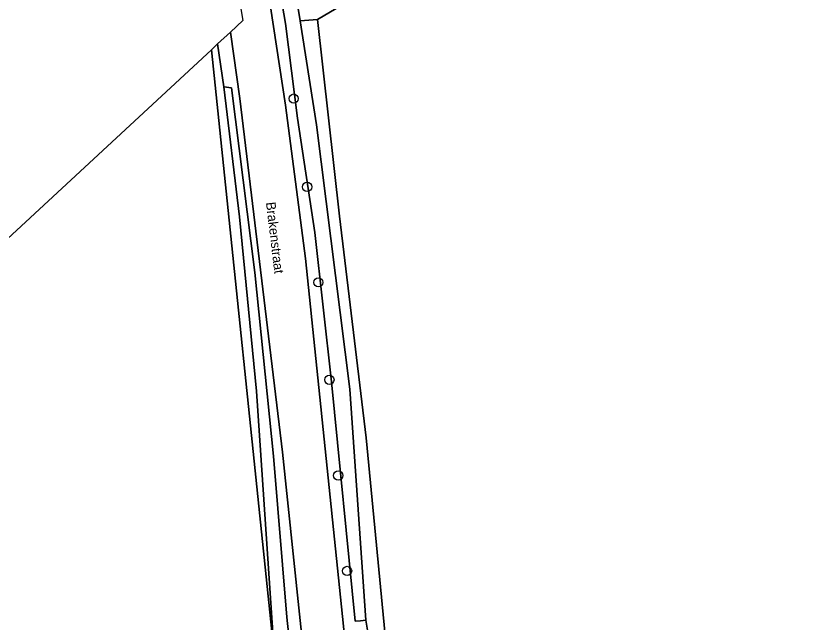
# Model space of a CAD drawing. Extents: x 163859 to 164644, y 379566 to 382155.
# Drawn here: x 164337.9 to 164422.2, y 382026.8 to 382090.8 of the extents above; entities that cross this region are included whole.
import ezdxf

# ---------------------------------------------------------------- set-up
doc = ezdxf.new("R2010")
doc.units = 0
for name, color, linetype in [('IMGEO_Boom', 7, 'Continuous'), ('IMGEO_Erf', 7, 'Continuous'), ('IMGEO_Grasland_agrarisch', 7, 'Continuous'), ('IMGEO_Grasland_overig', 7, 'Continuous'), ('IMGEO_Groenvoorziening', 7, 'Continuous'), ('IMGEO_Hek', 7, 'Continuous'), ('IMGEO_Loofbos', 7, 'Continuous'), ('IMGEO_Openbare_ruimte_label', 7, 'Continuous'), ('IMGEO_Rijbaan_lokaal_halfverhard', 7, 'Continuous'), ('IMGEO_Waterloop', 7, 'Continuous')]:
    doc.layers.add(name, color=color, linetype=linetype)

msp = doc.modelspace()

# ---------------------------------------------------------------- linework, layer by layer
at = {"layer": 'IMGEO_Boom'}
for centre in [(164367.083, 382082.063), (164368.496, 382072.769), (164369.681, 382062.713), (164370.841, 382052.454), (164371.772, 382042.372), (164372.703, 382032.316)]:
    msp.add_circle(centre, 0.489, dxfattribs=at)
at = {"layer": 'IMGEO_Erf'}
msp.add_lwpolyline([(164367.356, 382092.892), (164367.768, 382090.275), (164369.59, 382090.415), (164373.957, 382092.98)], dxfattribs=at)
msp.add_lwpolyline([(164358.416, 382087.209), (164254.852, 381991.262), (164247.66, 381997.032), (164147.193, 381903.339), (164170.551, 381887.103), (164176.8, 381882.795), (164180.902, 381879.968), (164183.031, 381877.576), (164194.945, 381868.909), (164195.394, 381868.583), (164197.248, 381870.262), (164204.736, 381876.958), (164229.912, 381895.792), (164270.687, 381927.48), (164301.861, 381952.134), (164302.429, 381952.58), (164302.08, 381953.025), (164345.159, 381986.829), (164370.617, 381969.688), (164370.447, 381973.615), (164369.98, 381979.405), (164367.666, 382000), (164365.056, 382023.236)], close=True, dxfattribs=at)
at = {"layer": 'IMGEO_Grasland_agrarisch'}
msp.add_lwpolyline([(164435.91, 382115.587), (164393.78, 382126.007), (164393.977, 382126.658), (164393.22, 382126.843), (164389.6, 382112.906), (164387.831, 382106.038), (164385.986, 382095.611), (164373.957, 382092.98), (164369.59, 382090.415), (164371.919, 382069.694), (164374.733, 382046.331), (164377.32, 382019.353)], dxfattribs=at)
at = {"layer": 'IMGEO_Grasland_overig'}
msp.add_lwpolyline([(164380.198, 381977.725), (164381.786, 381978.083), (164380.199, 381990.41), (164377.32, 382019.353), (164374.733, 382046.331), (164371.919, 382069.694), (164369.59, 382090.415), (164367.768, 382090.275), (164368.053, 382088.47), (164369.499, 382079.302), (164372.988, 382051.449), (164374.694, 382027.134), (164374.98, 382025.233), (164375.002, 382024.987), (164377.319, 381999.913), (164378.624, 381987.802), (164379.45, 381980.132), (164379.718, 381978.949), (164379.996, 381979.003)], close=True, dxfattribs=at)
at = {"layer": 'IMGEO_Groenvoorziening'}
for points in [[(164377.319, 381999.913), (164375.002, 382024.987), (164374.98, 382025.233), (164374.694, 382027.134), (164374.125, 382027.073), (164373.556, 382027.013), (164371.068, 382052.247), (164369.311, 382067.964), (164367.499, 382080), (164366.209, 382089.978), (164363.361, 382106.673), (164361.941, 382106.41), (164362.186, 382105.089), (164364.658, 382091.736), (164366.228, 382081.359), (164368.326, 382065.243), (164375.071, 382000), (164376.328, 381987.84), (164377.032, 381983.081), (164379.466, 381969.665), (164387.742, 381919.592), (164388.097, 381917.443), (164394.676, 381881.88)], [(164390.517, 381880.761), (164384.136, 381916.838), (164383.707, 381918.929), (164381.308, 381930.613), (164377.519, 381953.775), (164372.697, 381981.957), (164370.619, 382000), (164365.911, 382044.843), (164361.432, 382082.094), (164360.434, 382089.079), (164359.078, 382087.822)], [(164359.078, 382087.822), (164359.748, 382083.296), (164360.535, 382083.195), (164363.006, 382063.744), (164364.969, 382044.418), (164366.369, 382027.454), (164369.266, 382000), (164371.037, 381984.969), (164371.583, 381977.884), (164371.641, 381973.465), (164370.447, 381973.615), (164370.617, 381969.688), (164370.71, 381967.541), (164371.118, 381967.241), (164372.161, 381966.252), (164373.868, 381962.902), (164374.838, 381959.882), (164376.195, 381953.331), (164377.657, 381944.748), (164380.303, 381933.648), (164382.518, 381922.103)]]:
    msp.add_lwpolyline(points, dxfattribs=at)
at = {"layer": 'IMGEO_Hek'}
msp.add_lwpolyline([(164358.416, 382087.209), (164365.056, 382023.236)], dxfattribs=at)
at = {"layer": 'IMGEO_Loofbos'}
msp.add_lwpolyline([(164359.078, 382087.822), (164358.416, 382087.209), (164365.056, 382023.236), (164363.18, 382051.248), (164361.396, 382069.608), (164359.748, 382083.296)], close=True, dxfattribs=at)
at = {"layer": 'IMGEO_Rijbaan_lokaal_halfverhard'}
for points in [[(164394.676, 381881.88), (164388.097, 381917.443), (164387.742, 381919.592), (164379.466, 381969.665), (164377.032, 381983.081), (164376.328, 381987.84), (164375.071, 382000), (164368.326, 382065.243), (164366.228, 382081.359), (164364.658, 382091.736), (164362.186, 382105.089), (164359.316, 382104.565), (164361.733, 382090.282), (164360.434, 382089.079)], [(164360.434, 382089.079), (164361.432, 382082.094), (164365.911, 382044.843), (164370.619, 382000), (164372.697, 381981.957), (164377.519, 381953.775), (164381.308, 381930.613), (164383.707, 381918.929), (164384.136, 381916.838), (164390.517, 381880.761)]]:
    msp.add_lwpolyline(points, dxfattribs=at)
at = {"layer": 'IMGEO_Waterloop'}
for points in [[(164363.361, 382106.673), (164366.209, 382089.978), (164367.499, 382080), (164369.311, 382067.964), (164371.068, 382052.247), (164373.556, 382027.013), (164374.125, 382027.073), (164374.694, 382027.134), (164372.988, 382051.449), (164369.499, 382079.302), (164368.053, 382088.47), (164367.768, 382090.275), (164367.356, 382092.892), (164366.273, 382099.763), (164365.725, 382102.336), (164365.199, 382106.995), (164364.28, 382106.834)], [(164370.447, 381973.615), (164371.641, 381973.465), (164371.583, 381977.884), (164371.037, 381984.969), (164369.266, 382000), (164366.369, 382027.454), (164364.969, 382044.418), (164363.006, 382063.744), (164360.535, 382083.195), (164359.748, 382083.296), (164361.396, 382069.608), (164363.18, 382051.248), (164365.056, 382023.236), (164367.666, 382000), (164369.98, 381979.405)]]:
    msp.add_lwpolyline(points, close=True, dxfattribs=at)

# ---------------------------------------------------------------- texts
at = {"layer": 'IMGEO_Openbare_ruimte_label'}
msp.add_text('Brakenstraat', height=1, rotation=276.83367, dxfattribs=at).set_placement((164364.163, 382071.12))

doc.saveas('drawing.dxf')
